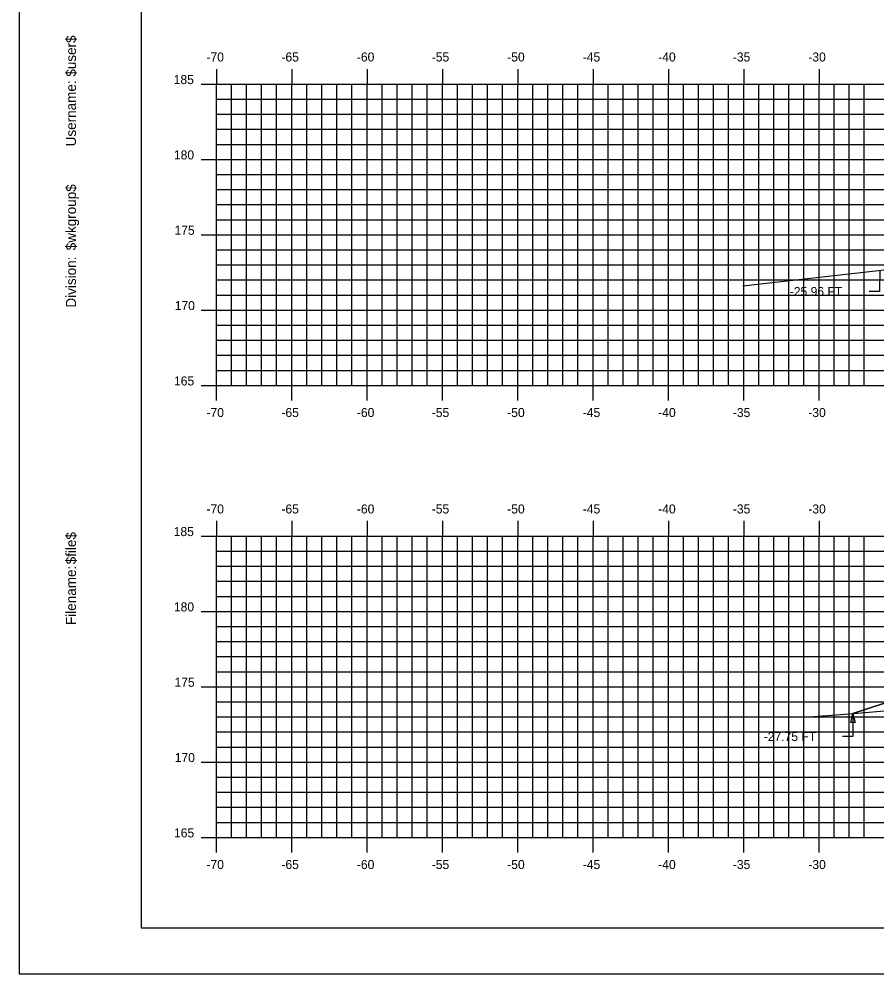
# Model space of a CAD drawing. Extents: x 1140315 to 1140485, y 608981 to 609091.
# Drawn here: x 1140315.4 to 1140372.3, y 608981.3 to 609044.6 of the extents above; entities that cross this region are included whole.
import ezdxf

# ---------------------------------------------------------------- set-up
doc = ezdxf.new("R2010")
doc.units = 0
for name, color, linetype in [('BORDER', 7, 'Continuous'), ('D_Roadway_SlopeLines', 7, 'Continuous'), ('D_Text_Standard', 7, 'Continuous'), ('H_V ANNOTATION', 7, 'Continuous'), ('MAJOR', 7, 'Continuous'), ('MINOR', 7, 'Continuous'), ('PLOT BOUNDARY', 7, 'Continuous'), ('S_Roadway_Centerline', 7, 'Continuous')]:
    doc.layers.add(name, color=color, linetype=linetype)

msp = doc.modelspace()

# ---------------------------------------------------------------- linework, layer by layer
msp.add_lwpolyline([(1140370.736, 608998.555), (1140372.763, 608999.23), (1140375.763, 609000.23), (1140383.487, 609002.805), (1140383.488, 609002.805), (1140387.488, 609002.965), (1140398.488, 609003.185), (1140409.488, 609002.965), (1140413.488, 609002.805), (1140421.211, 609000.23), (1140424.211, 608999.23), (1140426.373, 609000.311), (1140427.623, 609000.863), (1140428.873, 609001.27), (1140430.123, 609001.531), (1140431.373, 609001.646)])
at = {"layer": 'BORDER'}
msp.add_lwpolyline([(1140323.488, 608984.335), (1140483.488, 608984.335), (1140483.488, 609089.335), (1140323.488, 609089.335)], close=True, dxfattribs=at)
at = {"layer": 'D_Roadway_SlopeLines'}
msp.add_lwpolyline([(1140372.763, 608999.23), (1140370.736, 608998.555)], dxfattribs=at)
at = {"layer": 'D_Text_Standard'}
for points in [[(1140372.532, 609027.976), (1140372.501, 609026.568), (1140371.821, 609026.568)], [(1140370.736, 608998.555), (1140370.729, 608997.03), (1140370.049, 608997.03)]]:
    msp.add_lwpolyline(points, dxfattribs=at)
msp.add_lwpolyline([(1140370.736, 608998.555), (1140370.879, 608997.972), (1140370.588, 608997.973)], close=True, dxfattribs=at)
at = {"layer": 'MAJOR'}
for p, q in [((1140328.488, 609041.337), (1140328.488, 609040.335)), ((1140333.488, 609041.337), (1140333.488, 609040.335)), ((1140338.488, 609041.337), (1140338.488, 609040.335)), ((1140343.488, 609041.337), (1140343.488, 609040.335)), ((1140348.488, 609041.337), (1140348.488, 609040.335)), ((1140353.488, 609041.337), (1140353.488, 609040.335)), ((1140358.488, 609041.337), (1140358.488, 609040.335)), ((1140363.488, 609041.337), (1140363.488, 609040.335)), ((1140368.488, 609041.337), (1140368.488, 609040.335)), ((1140327.486, 609040.335), (1140328.488, 609040.335)), ((1140328.488, 609040.335), (1140468.488, 609040.335)), ((1140328.488, 609020.335), (1140328.488, 609040.335)), ((1140328.488, 609020.335), (1140328.488, 609040.335)), ((1140328.488, 609040.335), (1140468.488, 609040.335)), ((1140333.488, 609020.335), (1140333.488, 609040.335)), ((1140338.488, 609020.335), (1140338.488, 609040.335)), ((1140343.488, 609020.335), (1140343.488, 609040.335)), ((1140348.488, 609020.335), (1140348.488, 609040.335)), ((1140353.488, 609020.335), (1140353.488, 609040.335)), ((1140358.488, 609020.335), (1140358.488, 609040.335)), ((1140363.488, 609020.335), (1140363.488, 609040.335)), ((1140368.488, 609020.335), (1140368.488, 609040.335)), ((1140327.486, 609035.335), (1140328.488, 609035.335)), ((1140328.488, 609035.335), (1140468.488, 609035.335)), ((1140327.486, 609030.335), (1140328.488, 609030.335)), ((1140328.488, 609030.335), (1140468.488, 609030.335)), ((1140327.486, 609025.335), (1140328.488, 609025.335)), ((1140328.488, 609025.335), (1140468.488, 609025.335)), ((1140327.486, 609020.335), (1140328.488, 609020.335)), ((1140328.488, 609020.335), (1140468.488, 609020.335)), ((1140328.488, 609020.335), (1140468.488, 609020.335)), ((1140328.488, 609019.333), (1140328.488, 609020.335)), ((1140333.488, 609019.333), (1140333.488, 609020.335)), ((1140338.488, 609019.333), (1140338.488, 609020.335)), ((1140343.488, 609019.333), (1140343.488, 609020.335)), ((1140348.488, 609019.333), (1140348.488, 609020.335)), ((1140353.488, 609019.333), (1140353.488, 609020.335)), ((1140358.488, 609019.333), (1140358.488, 609020.335)), ((1140363.488, 609019.333), (1140363.488, 609020.335)), ((1140368.488, 609019.333), (1140368.488, 609020.335)), ((1140328.488, 609011.337), (1140328.488, 609010.335)), ((1140333.488, 609011.337), (1140333.488, 609010.335)), ((1140338.488, 609011.337), (1140338.488, 609010.335)), ((1140343.488, 609011.337), (1140343.488, 609010.335)), ((1140348.488, 609011.337), (1140348.488, 609010.335)), ((1140353.488, 609011.337), (1140353.488, 609010.335)), ((1140358.488, 609011.337), (1140358.488, 609010.335)), ((1140363.488, 609011.337), (1140363.488, 609010.335)), ((1140368.488, 609011.337), (1140368.488, 609010.335)), ((1140327.486, 609010.335), (1140328.488, 609010.335)), ((1140328.488, 609010.335), (1140468.488, 609010.335)), ((1140328.488, 608990.335), (1140328.488, 609010.335)), ((1140328.488, 608990.335), (1140328.488, 609010.335)), ((1140328.488, 609010.335), (1140468.488, 609010.335)), ((1140333.488, 608990.335), (1140333.488, 609010.335)), ((1140338.488, 608990.335), (1140338.488, 609010.335)), ((1140343.488, 608990.335), (1140343.488, 609010.335)), ((1140348.488, 608990.335), (1140348.488, 609010.335)), ((1140353.488, 608990.335), (1140353.488, 609010.335)), ((1140358.488, 608990.335), (1140358.488, 609010.335)), ((1140363.488, 608990.335), (1140363.488, 609010.335)), ((1140368.488, 608990.335), (1140368.488, 609010.335)), ((1140327.486, 609005.335), (1140328.488, 609005.335)), ((1140328.488, 609005.335), (1140468.488, 609005.335)), ((1140327.486, 609000.335), (1140328.488, 609000.335)), ((1140328.488, 609000.335), (1140468.488, 609000.335)), ((1140327.486, 608995.335), (1140328.488, 608995.335)), ((1140328.488, 608995.335), (1140468.488, 608995.335)), ((1140327.486, 608990.335), (1140328.488, 608990.335)), ((1140328.488, 608990.335), (1140468.488, 608990.335)), ((1140328.488, 608990.335), (1140468.488, 608990.335)), ((1140328.488, 608989.333), (1140328.488, 608990.335)), ((1140333.488, 608989.333), (1140333.488, 608990.335)), ((1140338.488, 608989.333), (1140338.488, 608990.335)), ((1140343.488, 608989.333), (1140343.488, 608990.335)), ((1140348.488, 608989.333), (1140348.488, 608990.335)), ((1140353.488, 608989.333), (1140353.488, 608990.335)), ((1140358.488, 608989.333), (1140358.488, 608990.335)), ((1140363.488, 608989.333), (1140363.488, 608990.335)), ((1140368.488, 608989.333), (1140368.488, 608990.335))]:
    msp.add_line(p, q, dxfattribs=at)
at = {"layer": 'MINOR'}
for p, q in [((1140329.488, 609020.335), (1140329.488, 609040.335)), ((1140330.488, 609020.335), (1140330.488, 609040.335)), ((1140331.488, 609020.335), (1140331.488, 609040.335)), ((1140332.488, 609020.335), (1140332.488, 609040.335)), ((1140334.488, 609020.335), (1140334.488, 609040.335)), ((1140335.488, 609020.335), (1140335.488, 609040.335)), ((1140336.488, 609020.335), (1140336.488, 609040.335)), ((1140337.488, 609020.335), (1140337.488, 609040.335)), ((1140339.488, 609020.335), (1140339.488, 609040.335)), ((1140340.488, 609020.335), (1140340.488, 609040.335)), ((1140341.488, 609020.335), (1140341.488, 609040.335)), ((1140342.488, 609020.335), (1140342.488, 609040.335)), ((1140344.488, 609020.335), (1140344.488, 609040.335)), ((1140345.488, 609020.335), (1140345.488, 609040.335)), ((1140346.488, 609020.335), (1140346.488, 609040.335)), ((1140347.488, 609020.335), (1140347.488, 609040.335)), ((1140349.488, 609020.335), (1140349.488, 609040.335)), ((1140350.488, 609020.335), (1140350.488, 609040.335)), ((1140351.488, 609020.335), (1140351.488, 609040.335)), ((1140352.488, 609020.335), (1140352.488, 609040.335)), ((1140354.488, 609020.335), (1140354.488, 609040.335)), ((1140355.488, 609020.335), (1140355.488, 609040.335)), ((1140356.488, 609020.335), (1140356.488, 609040.335)), ((1140357.488, 609020.335), (1140357.488, 609040.335)), ((1140359.488, 609020.335), (1140359.488, 609040.335)), ((1140360.488, 609020.335), (1140360.488, 609040.335)), ((1140361.488, 609020.335), (1140361.488, 609040.335)), ((1140362.488, 609020.335), (1140362.488, 609040.335)), ((1140364.488, 609020.335), (1140364.488, 609040.335)), ((1140365.488, 609020.335), (1140365.488, 609040.335)), ((1140366.488, 609020.335), (1140366.488, 609040.335)), ((1140367.488, 609020.335), (1140367.488, 609040.335)), ((1140369.488, 609020.335), (1140369.488, 609040.335)), ((1140370.488, 609020.335), (1140370.488, 609040.335)), ((1140371.488, 609020.335), (1140371.488, 609040.335)), ((1140328.488, 609039.335), (1140468.488, 609039.335)), ((1140328.488, 609039.335), (1140329.49, 609039.335)), ((1140328.488, 609038.335), (1140468.488, 609038.335)), ((1140328.488, 609038.335), (1140329.49, 609038.335)), ((1140328.488, 609037.335), (1140468.488, 609037.335)), ((1140328.488, 609037.335), (1140329.49, 609037.335)), ((1140328.488, 609036.335), (1140468.488, 609036.335)), ((1140328.488, 609036.335), (1140329.49, 609036.335)), ((1140328.488, 609034.335), (1140468.488, 609034.335)), ((1140328.488, 609034.335), (1140329.49, 609034.335)), ((1140328.488, 609033.335), (1140468.488, 609033.335)), ((1140328.488, 609033.335), (1140329.49, 609033.335)), ((1140328.488, 609032.335), (1140468.488, 609032.335)), ((1140328.488, 609032.335), (1140329.49, 609032.335)), ((1140328.488, 609031.335), (1140468.488, 609031.335)), ((1140328.488, 609031.335), (1140329.49, 609031.335)), ((1140328.488, 609029.335), (1140468.488, 609029.335)), ((1140328.488, 609029.335), (1140329.49, 609029.335)), ((1140328.488, 609028.335), (1140468.488, 609028.335)), ((1140328.488, 609028.335), (1140329.49, 609028.335)), ((1140328.488, 609027.335), (1140468.488, 609027.335)), ((1140328.488, 609027.335), (1140329.49, 609027.335)), ((1140328.488, 609026.335), (1140468.488, 609026.335)), ((1140328.488, 609026.335), (1140329.49, 609026.335)), ((1140328.488, 609024.335), (1140468.488, 609024.335)), ((1140328.488, 609024.335), (1140329.49, 609024.335)), ((1140328.488, 609023.335), (1140468.488, 609023.335)), ((1140328.488, 609023.335), (1140329.49, 609023.335)), ((1140328.488, 609022.335), (1140468.488, 609022.335)), ((1140328.488, 609022.335), (1140329.49, 609022.335)), ((1140328.488, 609021.335), (1140468.488, 609021.335)), ((1140328.488, 609021.335), (1140329.49, 609021.335)), ((1140329.488, 608990.335), (1140329.488, 609010.335)), ((1140330.488, 608990.335), (1140330.488, 609010.335)), ((1140331.488, 608990.335), (1140331.488, 609010.335)), ((1140332.488, 608990.335), (1140332.488, 609010.335)), ((1140334.488, 608990.335), (1140334.488, 609010.335)), ((1140335.488, 608990.335), (1140335.488, 609010.335)), ((1140336.488, 608990.335), (1140336.488, 609010.335)), ((1140337.488, 608990.335), (1140337.488, 609010.335)), ((1140339.488, 608990.335), (1140339.488, 609010.335)), ((1140340.488, 608990.335), (1140340.488, 609010.335)), ((1140341.488, 608990.335), (1140341.488, 609010.335)), ((1140342.488, 608990.335), (1140342.488, 609010.335)), ((1140344.488, 608990.335), (1140344.488, 609010.335)), ((1140345.488, 608990.335), (1140345.488, 609010.335)), ((1140346.488, 608990.335), (1140346.488, 609010.335)), ((1140347.488, 608990.335), (1140347.488, 609010.335)), ((1140349.488, 608990.335), (1140349.488, 609010.335)), ((1140350.488, 608990.335), (1140350.488, 609010.335)), ((1140351.488, 608990.335), (1140351.488, 609010.335)), ((1140352.488, 608990.335), (1140352.488, 609010.335)), ((1140354.488, 608990.335), (1140354.488, 609010.335)), ((1140355.488, 608990.335), (1140355.488, 609010.335)), ((1140356.488, 608990.335), (1140356.488, 609010.335)), ((1140357.488, 608990.335), (1140357.488, 609010.335)), ((1140359.488, 608990.335), (1140359.488, 609010.335)), ((1140360.488, 608990.335), (1140360.488, 609010.335)), ((1140361.488, 608990.335), (1140361.488, 609010.335)), ((1140362.488, 608990.335), (1140362.488, 609010.335)), ((1140364.488, 608990.335), (1140364.488, 609010.335)), ((1140365.488, 608990.335), (1140365.488, 609010.335)), ((1140366.488, 608990.335), (1140366.488, 609010.335)), ((1140367.488, 608990.335), (1140367.488, 609010.335)), ((1140369.488, 608990.335), (1140369.488, 609010.335)), ((1140370.488, 608990.335), (1140370.488, 609010.335)), ((1140371.488, 608990.335), (1140371.488, 609010.335)), ((1140328.488, 609009.335), (1140468.488, 609009.335)), ((1140328.488, 609009.335), (1140329.49, 609009.335)), ((1140328.488, 609008.335), (1140468.488, 609008.335)), ((1140328.488, 609008.335), (1140329.49, 609008.335)), ((1140328.488, 609007.335), (1140468.488, 609007.335)), ((1140328.488, 609007.335), (1140329.49, 609007.335)), ((1140328.488, 609006.335), (1140468.488, 609006.335)), ((1140328.488, 609006.335), (1140329.49, 609006.335)), ((1140328.488, 609004.335), (1140468.488, 609004.335)), ((1140328.488, 609004.335), (1140329.49, 609004.335)), ((1140328.488, 609003.335), (1140468.488, 609003.335)), ((1140328.488, 609003.335), (1140329.49, 609003.335)), ((1140328.488, 609002.335), (1140468.488, 609002.335)), ((1140328.488, 609002.335), (1140329.49, 609002.335)), ((1140328.488, 609001.335), (1140468.488, 609001.335)), ((1140328.488, 609001.335), (1140329.49, 609001.335)), ((1140328.488, 608999.335), (1140468.488, 608999.335)), ((1140328.488, 608999.335), (1140329.49, 608999.335)), ((1140328.488, 608998.335), (1140468.488, 608998.335)), ((1140328.488, 608998.335), (1140329.49, 608998.335)), ((1140328.488, 608997.335), (1140468.488, 608997.335)), ((1140328.488, 608997.335), (1140329.49, 608997.335)), ((1140328.488, 608996.335), (1140468.488, 608996.335)), ((1140328.488, 608996.335), (1140329.49, 608996.335)), ((1140328.488, 608994.335), (1140468.488, 608994.335)), ((1140328.488, 608994.335), (1140329.49, 608994.335)), ((1140328.488, 608993.335), (1140468.488, 608993.335)), ((1140328.488, 608993.335), (1140329.49, 608993.335)), ((1140328.488, 608992.335), (1140468.488, 608992.335)), ((1140328.488, 608992.335), (1140329.49, 608992.335)), ((1140328.488, 608991.335), (1140468.488, 608991.335)), ((1140328.488, 608991.335), (1140329.49, 608991.335))]:
    msp.add_line(p, q, dxfattribs=at)
at = {"layer": 'PLOT BOUNDARY'}
msp.add_lwpolyline([(1140315.395, 608981.276), (1140485.395, 608981.276), (1140485.395, 609091.276), (1140315.395, 609091.276)], close=True, dxfattribs=at)
at = {"layer": 'S_Roadway_Centerline'}
for points in [[(1140363.42, 609026.944), (1140373.015, 609028.03), (1140377.783, 609028.374), (1140383.357, 609030.919), (1140384.446, 609031.317), (1140386.704, 609031.7), (1140387.162, 609031.789), (1140388.836, 609031.847), (1140398.293, 609032.157), (1140403.918, 609032.055), (1140409.283, 609031.936), (1140410.508, 609031.768), (1140411.694, 609031.611), (1140418.287, 609030.462), (1140419.066, 609030.326), (1140423.927, 609030.429), (1140424.22, 609030.421), (1140427.364, 609030.537), (1140450.895, 609031.63), (1140457.789, 609031.917), (1140468.488, 609032.187)], [(1140367.542, 608998.327), (1140370.795, 608998.559), (1140377.85, 608999.184), (1140382.728, 609001.243), (1140384.55, 609001.921), (1140386.861, 609002.265), (1140387.461, 609002.383), (1140389.636, 609002.458), (1140393.842, 609002.696), (1140398.506, 609003.008), (1140403.767, 609002.674), (1140409.646, 609002.543), (1140411.009, 609002.36), (1140411.793, 609002.182), (1140414.446, 609001.638), (1140417.551, 609001.002), (1140420.367, 609001.06), (1140422.978, 609001.362), (1140440.501, 609001.955), (1140446.381, 609002.087), (1140464.846, 609002.691), (1140468.488, 609002.74)]]:
    msp.add_lwpolyline(points, dxfattribs=at)

# ---------------------------------------------------------------- texts
at = {"layer": 'BORDER'}
for s, p in [('$user$', (1140319.173, 609040.827)), ('Username:', (1140319.173, 609036.203)), ('$wkgroup$', (1140319.173, 609029.305)), ('Division:', (1140319.173, 609025.501)), ('$file$', (1140319.173, 609008.461)), ('Filename:', (1140319.173, 609004.433))]:
    msp.add_text(s, height=0.6696, rotation=90, dxfattribs=at).set_placement(p)
at = {"layer": 'D_Text_Standard'}
for s, p in [('-25.96 FT', (1140366.548, 609026.268)), ('-27.75 FT', (1140364.818, 608996.73))]:
    msp.add_text(s, height=0.6, dxfattribs=at).set_placement(p)
at = {"layer": 'H_V ANNOTATION'}
for s, p in [('-70', (1140327.83, 609041.835)), ('-65', (1140332.806, 609041.835)), ('-60', (1140337.814, 609041.835)), ('-55', (1140342.784, 609041.835)), ('-50', (1140347.792, 609041.835)), ('-45', (1140352.806, 609041.835)), ('-40', (1140357.814, 609041.835)), ('-35', (1140362.768, 609041.835)), ('-30', (1140367.776, 609041.835)), ('185', (1140325.655, 609040.335)), ('180', (1140325.671, 609035.335)), ('175', (1140325.709, 609030.335)), ('170', (1140325.725, 609025.335)), ('165', (1140325.677, 609020.335)), ('-70', (1140327.83, 609018.235)), ('-65', (1140332.806, 609018.235)), ('-60', (1140337.814, 609018.235)), ('-55', (1140342.784, 609018.235)), ('-50', (1140347.792, 609018.235)), ('-45', (1140352.806, 609018.235)), ('-40', (1140357.814, 609018.235)), ('-35', (1140362.768, 609018.235)), ('-30', (1140367.776, 609018.235)), ('-70', (1140327.83, 609011.835)), ('-65', (1140332.806, 609011.835)), ('-60', (1140337.814, 609011.835)), ('-55', (1140342.784, 609011.835)), ('-50', (1140347.792, 609011.835)), ('-45', (1140352.806, 609011.835)), ('-40', (1140357.814, 609011.835)), ('-35', (1140362.768, 609011.835)), ('-30', (1140367.776, 609011.835)), ('185', (1140325.655, 609010.335)), ('180', (1140325.671, 609005.335)), ('175', (1140325.709, 609000.335)), ('170', (1140325.725, 608995.335)), ('165', (1140325.677, 608990.335)), ('-70', (1140327.83, 608988.235)), ('-65', (1140332.806, 608988.235)), ('-60', (1140337.814, 608988.235)), ('-55', (1140342.784, 608988.235)), ('-50', (1140347.792, 608988.235)), ('-45', (1140352.806, 608988.235)), ('-40', (1140357.814, 608988.235)), ('-35', (1140362.768, 608988.235)), ('-30', (1140367.776, 608988.235))]:
    msp.add_text(s, height=0.6, dxfattribs=at).set_placement(p)
at = {"layer": 'MAJOR'}
for p in [(1140328.483, 609020.335), (1140328.483, 608990.335)]:
    msp.add_text('-', height=0.006, dxfattribs=at).set_placement(p)

doc.saveas('drawing.dxf')
